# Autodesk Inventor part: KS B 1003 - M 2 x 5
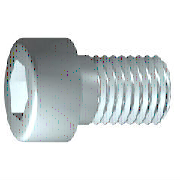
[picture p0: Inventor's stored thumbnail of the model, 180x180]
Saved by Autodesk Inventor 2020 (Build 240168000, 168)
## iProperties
Created: 2019-01
Part Number: KS B 1003 - M 2 x 5
Material: Acier, doux
Description: Vis à tôle à tête hexagonale
Document SubType Name: Modeling
Standard: KS B 1003
Designer: bruno
Standards Organization: KS
Language: fr-FR
Size Designation: M 2 x 5
Categories: <MemberInstance><Categories><Category DisplayName="Visserie" InternalName="e4da775c-781d-43d5-af7c-5136215cf5a6" Mnemonic="FSTN"><Category DisplayName="Vis" Int
Density: 7.85 g/cm^3
Appearance: Semi-poli
IsCustomPart: 0
Author: bruno
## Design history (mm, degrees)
sketch "Esquisse1"
  geometry: L1 (-0.5, 0)-(5, 0); L2 (5, 0)-(5, 1); L3 (5, 1)-(1, 1); L4 (1, 1)-(0.755, 1); L5 (0.755, 1)-(0, 1); L6 (0, 1)-(0, 1.9); L7 (0, 1.9)-(-2, 1.9); L8 (-2, 1.9)-(-2, 0.866); L9 (-2, 0.866)-(-1, 0.866); L10 (-1, 0.866)-(-0.5, 0); L11 (-3.4, 0)-(6.4, 0) reference; L12 (0, -0.38)-(0, 2.28) reference; L13 (1, 1)-(0, 1)
  constraints: 22 end point, 6 parallel, 2 collinear, 2 perpendicular, 1 horizontal, 1 point on line
  dimensions: "d1" = 4 distance from line of L3.end L2 (= GEL); "d2" = 0.24548 distance of L4.end L3.end (computed from GAL); "d3" = 2 distance between parallel lines of L8 L6 (= KOH); "d4" = 1 distance of L8.end L9.end (= INTI); "d5" = 60 deg angle of L10 L1; "d6" = 2 diameter of L3 L1 (= GD); "d7" = 2 diameter of L5 L1 (= BDM); "d8" = 1.73205 diameter of L9 L1 (= 1.1547 x SW); "d9" = 3.8 diameter of L7 L1 (= KOD); "d26" = 5 distance between parallel lines of L12 L2 (= NLG)
revolve "Corps" sketch "Esquisse1" stored, may be unused: angle "d10" = 90 deg
sketch "Esquisse2"
  geometry: L1 (0, -2.66)-(0, 2.66) reference; L2 (-2.66, 0)-(2.66, 0) reference; L3 (0.866, 0)-(0.433, -0.75); L4 (0.433, -0.75)-(-0.433, -0.75); L5 (-0.433, -0.75)-(-0.866, 0); L6 (-0.866, 0)-(-0.433, 0.75); L7 (-0.433, 0.75)-(0.433, 0.75); L8 (0.433, 0.75)-(0.866, 0); 2 further points
  constraints: 12 end point, 1 coincident, 1 horizontal alignment, 1 point on line, 12 other
extrude "Rainure" join sketch "Esquisse2" stored distance "d11" = 10; taper "d12" = 0 deg
workplane "Work Plane1"
fillet "Fillet2" dims "d30" = 0.1 (= R)
body "Solid1"
fillet "Congé1" dims "d17" = 0.2 (= RR)
feature "Filetage" dims "d13" = 4 (= GEL), "d14" = 0
chamfer "Chanfrein1" distance "d15" = 0.24538 (= -0.5 x SPD + 0.5 x GD); stored, may be unused: second distance "d16" = 0.24538 (= GUL), angle "d27" = 45 deg
other parameters: "GD" = 2 (= NND) [user parameter; used in 2 equation terms], "NLG" = 5 [user parameter; used in 1 equation term], "GEL" = 4 [user parameter; used in 2 equation terms], "KOD" = 3.8 [user parameter; used in 1 equation term], "KOH" = 2 [user parameter; used in 1 equation term], "INTI" = 1 [user parameter; used in 1 equation term], "GAL" = 0.24538 (= 0.61345 x PTC) [user parameter; used in 1 equation term], "GUL" = 0.24538 (= 0.61345 x PTC) [user parameter; used in 1 equation term], "BDM" = 2 (= NND) [user parameter; used in 1 equation term], "SW" = 1.5 [user parameter; used in 2 equation terms], "RR" = 0.2 [user parameter; used in 1 equation term], "SPD" = 1.50924 (= NND - 1.2269 x PTC) [user parameter; used in 1 equation term], "d19" = 0, "d28" = 0, "d29" = 0, "R" = 0.1 [user parameter; used in 1 equation term], "PHH" = 0.1 [user parameter], "GD1" = 1.50924 (= THREADDIA - 1.2269 x PTC) [user parameter], "THREADDIA" = 2 [user parameter; used in 1 equation term], "FAWI" = 45 deg [user parameter], "TPU" = 25 (computed from PTC) [user parameter], "PTC" = 0.4 [user parameter; used in 5 equation terms], "NND" = 2 [user parameter; used in 3 equation terms], "TOA" = 30 deg [user parameter], "E0" = 1.7325 (= 1.155 x SW) [user parameter]
